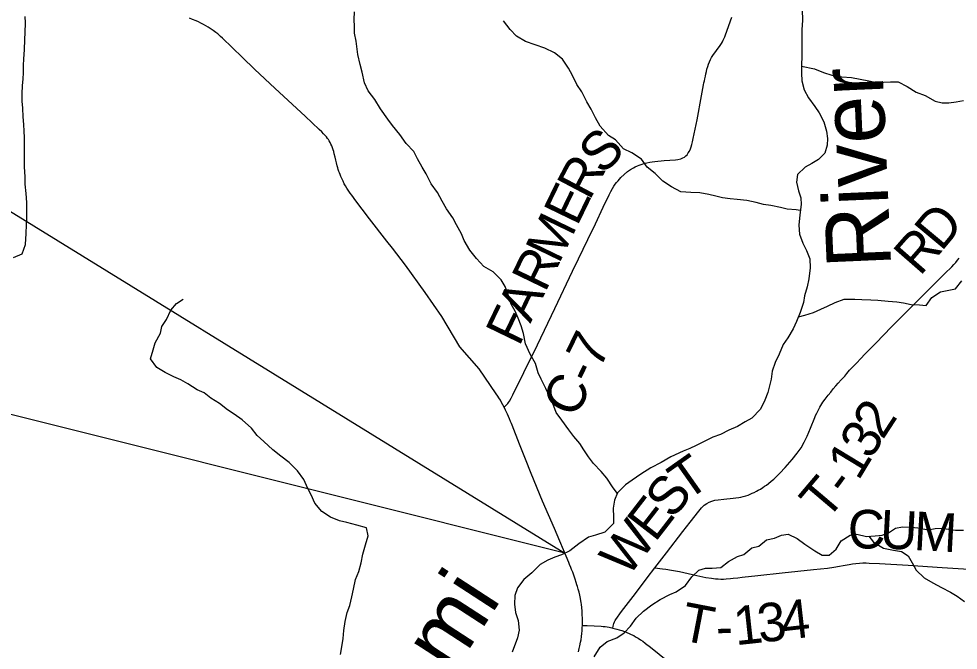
# Model space of a CAD drawing. Extents: x 0 to 48.6, y 0 to 22.
# Drawn here: x 4.141 to 5.524, y 17.631 to 18.56 of the extents above; entities that cross this region are included whole.
import ezdxf

# ---------------------------------------------------------------- set-up
doc = ezdxf.new("R2010")
doc.units = 0
for name, color, linetype in [('GM_X_County_Road', 7, 'Continuous'), ('GM_X_County_Road_Text', 7, 'Continuous'), ('GM_X_Major_River', 7, 'Continuous'), ('GM_X_Major_River_Text', 7, 'Continuous'), ('GM_X_Minor_River', 7, 'Continuous'), ('GM_X_State_Route', 7, 'Continuous'), ('GM_X_Township_Road', 7, 'Continuous'), ('GM_X_Township_Road_Text', 7, 'Continuous'), ('SH_Text', 7, 'Continuous')]:
    doc.layers.add(name, color=color, linetype=linetype)

msp = doc.modelspace()

# ---------------------------------------------------------------- linework, layer by layer
at = {"layer": 'GM_X_County_Road'}
msp.add_lwpolyline([(4.8552, 17.9885), (4.8569, 17.9902), (4.8598, 17.993), (4.8608, 17.994), (4.8619, 17.9954), (4.8632, 17.9975), (4.8656, 18.002), (4.8682, 18.0068), (4.8842, 18.0398), (4.9042, 18.0805), (4.9299, 18.1336), (4.9561, 18.1886), (4.965, 18.207), (4.9787, 18.2356), (4.9898, 18.2585), (5.001, 18.2828), (5.0099, 18.3012), (5.0123, 18.3059), (5.0148, 18.3105), (5.0169, 18.3137), (5.0188, 18.3166), (5.0209, 18.3193), (5.023, 18.3219), (5.0271, 18.3264), (5.032, 18.3311), (5.0371, 18.3354), (5.0411, 18.3383), (5.0458, 18.3411), (5.0482, 18.3423), (5.0514, 18.3438), (5.054, 18.3448), (5.0571, 18.346), (5.0624, 18.3477), (5.0656, 18.3484), (5.0696, 18.3492), (5.0732, 18.3498), (5.0769, 18.3503), (5.0911, 18.3516), (5.1078, 18.3527), (5.111, 18.3531), (5.1153, 18.3542), (5.1183, 18.3554), (5.1206, 18.3567), (5.1227, 18.3583), (5.1245, 18.3602), (5.1264, 18.3627), (5.128, 18.3655), (5.1296, 18.369), (5.1305, 18.3719), (5.1316, 18.375), (5.1326, 18.379), (5.1338, 18.3841), (5.1393, 18.4116), (5.1459, 18.447), (5.1488, 18.4629), (5.1495, 18.4659), (5.1501, 18.469), (5.1507, 18.472), (5.1515, 18.476), (5.1523, 18.4793), (5.153, 18.4826), (5.1538, 18.4859), (5.155, 18.4901), (5.156, 18.4936), (5.1575, 18.497), (5.1589, 18.5003), (5.1606, 18.5032), (5.1623, 18.5061), (5.1734, 18.5211), (5.1752, 18.5241), (5.1767, 18.5264), (5.1777, 18.5286), (5.1789, 18.531), (5.1801, 18.5339), (5.1813, 18.5368), (5.1903, 18.5626)], dxfattribs=at)
at = {"layer": 'GM_X_Major_River'}
msp.add_lwpolyline([(5.2942, 18.5735), (5.2943, 18.5584), (5.2936, 18.544), (5.2934, 18.5318), (5.2934, 18.5151), (5.2936, 18.5049), (5.2929, 18.4924), (5.293, 18.4802), (5.2936, 18.4688), (5.2971, 18.4558), (5.3033, 18.444), (5.3129, 18.4312), (5.3191, 18.4216), (5.3257, 18.4086), (5.33, 18.3948), (5.3313, 18.3842), (5.3307, 18.3743), (5.3274, 18.3626), (5.3181, 18.353), (5.3081, 18.3471), (5.2985, 18.342), (5.2873, 18.3308), (5.2855, 18.3198), (5.2886, 18.3069), (5.2922, 18.2966), (5.2924, 18.2867), (5.2906, 18.2715), (5.2891, 18.2564), (5.29, 18.2431), (5.295, 18.2301), (5.3005, 18.219), (5.3051, 18.2067), (5.306, 18.1938), (5.3041, 18.1775), (5.3012, 18.1658), (5.2975, 18.1526), (5.2958, 18.1428), (5.291, 18.1281), (5.2857, 18.1145), (5.2806, 18.104), (5.2727, 18.0905), (5.266, 18.0808), (5.2604, 18.0668), (5.2545, 18.0541), (5.25, 18.0413), (5.2483, 18.0299), (5.2433, 18.0103), (5.2389, 17.9986), (5.2325, 17.9854), (5.2201, 17.9724), (5.2101, 17.9669), (5.199, 17.9603), (5.186, 17.9549), (5.1737, 17.9483), (5.1626, 17.9443), (5.1476, 17.9371), (5.138, 17.9323), (5.1285, 17.9276), (5.1189, 17.924), (5.1005, 17.9156), (5.0863, 17.9072), (5.0713, 17.8991), (5.0567, 17.8899), (5.044, 17.8811), (5.034, 17.8741), (5.0223, 17.8622), (5.0179, 17.8516), (5.0158, 17.8399), (5.0163, 17.8266), (5.0161, 17.8171), (5.0033, 17.8045), (4.9899, 17.8002), (4.9796, 17.7974), (4.9653, 17.7874), (4.9522, 17.7771), (4.9399, 17.7712), (4.93, 17.7676), (4.9197, 17.7633), (4.9085, 17.7567), (4.8961, 17.7448), (4.8845, 17.7348), (4.8748, 17.7225), (4.8711, 17.7115), (4.8705, 17.6986), (4.8721, 17.6865), (4.8757, 17.6746), (4.8773, 17.6602), (4.8751, 17.6492), (4.8671, 17.6281)], dxfattribs=at)
at = {"layer": 'GM_X_Minor_River'}
for points in [[(4.1328, 18.2087), (4.1458, 18.2142), (4.1506, 18.2282), (4.1515, 18.2441), (4.1521, 18.257), (4.1526, 18.2673), (4.1524, 18.2798), (4.1525, 18.29), (4.1516, 18.303), (4.1502, 18.3166), (4.15, 18.3277), (4.1494, 18.3425), (4.1492, 18.3527), (4.1493, 18.3622), (4.1491, 18.3732), (4.1493, 18.3854), (4.1486, 18.3949), (4.1484, 18.4047), (4.1474, 18.4158), (4.1468, 18.4287), (4.1458, 18.4389), (4.1455, 18.4496), (4.1461, 18.4621), (4.1474, 18.4716), (4.1479, 18.4814), (4.1476, 18.4917), (4.1481, 18.5012), (4.1494, 18.5144), (4.1497, 18.5296), (4.1502, 18.5399), (4.1507, 18.5543), (4.1501, 18.5638)], [(5.0221, 17.8616), (5.016, 17.87), (5.0067, 17.8842), (4.9981, 17.8938), (4.9868, 17.9057), (4.9794, 17.9153), (4.9727, 17.9256), (4.9667, 17.9352), (4.9581, 17.9455), (4.9503, 17.9551), (4.9402, 17.9693), (4.932, 17.9808), (4.9269, 17.9938), (4.9228, 18.0033), (4.9165, 18.0159), (4.9099, 18.0297), (4.9054, 18.0392), (4.9014, 18.0526), (4.8937, 18.0667), (4.8866, 18.0816), (4.8838, 18.0972), (4.8805, 18.1083), (4.8761, 18.1197), (4.8713, 18.13), (4.8658, 18.1403), (4.861, 18.1541), (4.8566, 18.1663), (4.8511, 18.1758), (4.8391, 18.1878), (4.8255, 18.1955), (4.8146, 18.2074), (4.8049, 18.2197), (4.7964, 18.2339), (4.7927, 18.2438), (4.7853, 18.2568), (4.7797, 18.2671), (4.7704, 18.2805), (4.7641, 18.292), (4.7574, 18.3046), (4.7477, 18.3173), (4.7403, 18.3322), (4.7348, 18.3417), (4.7277, 18.3543), (4.7222, 18.365), (4.7113, 18.3766), (4.7016, 18.39), (4.6908, 18.403), (4.684, 18.4126), (4.6732, 18.4279), (4.6651, 18.4413), (4.655, 18.4544), (4.6498, 18.4662), (4.6462, 18.4818), (4.6433, 18.4929), (4.6401, 18.5077), (4.6373, 18.5275), (4.6352, 18.5393), (4.635, 18.5488), (4.6347, 18.559), (4.6349, 18.5704)], [(5.2913, 18.278), (5.2851, 18.2792), (5.2722, 18.2801), (5.2619, 18.2825), (5.2479, 18.2853), (5.2369, 18.287), (5.2263, 18.2898), (5.2127, 18.2926), (5.1983, 18.2943), (5.188, 18.2952), (5.1767, 18.2969), (5.1668, 18.2993), (5.1566, 18.3017), (5.1433, 18.3042), (5.1301, 18.3047), (5.1156, 18.3053), (5.1017, 18.3127), (5.0889, 18.3212), (5.0776, 18.3327), (5.066, 18.3416), (5.0574, 18.3535), (5.0431, 18.3628), (5.031, 18.369), (5.019, 18.3821), (5.0089, 18.3883), (4.9969, 18.4021), (4.9898, 18.4143), (4.9836, 18.4273), (4.9769, 18.438), (4.9695, 18.4526), (4.9624, 18.4633), (4.9561, 18.477), (4.9498, 18.4877), (4.9412, 18.5008), (4.9296, 18.51), (4.9152, 18.517), (4.9012, 18.5218), (4.8865, 18.5269), (4.8733, 18.5347), (4.8643, 18.5447), (4.8542, 18.5573)], [(5.2929, 18.4903), (5.3121, 18.4865), (5.3254, 18.4814), (5.3378, 18.4774), (5.3526, 18.4746), (5.3667, 18.4736), (5.3795, 18.4715), (5.3924, 18.4687), (5.4034, 18.4663), (5.4137, 18.4669), (5.4243, 18.4676), (5.4353, 18.4674), (5.4485, 18.4608), (5.4621, 18.4523), (5.4753, 18.4475), (5.4896, 18.439), (5.5002, 18.4366), (5.5101, 18.4364), (5.5208, 18.4378), (5.5314, 18.44)], [(5.2885, 18.1217), (5.2982, 18.1241), (5.3108, 18.1281), (5.3215, 18.1329), (5.3314, 18.1373), (5.3425, 18.1425), (5.3559, 18.1477), (5.3714, 18.1474), (5.3821, 18.1469), (5.395, 18.1464), (5.4056, 18.1459), (5.4208, 18.1445), (5.4333, 18.1436), (5.4431, 18.142), (5.4545, 18.1395), (5.467, 18.139), (5.4765, 18.1381), (5.4847, 18.1502), (5.4977, 18.1583), (5.5076, 18.1605), (5.5198, 18.1626), (5.529, 18.1743)], [(4.6146, 17.6243), (4.6163, 17.6356), (4.6184, 17.6481), (4.6193, 17.6599), (4.6214, 17.6731), (4.6242, 17.6864), (4.6281, 17.6966), (4.6313, 17.7095), (4.6334, 17.7208), (4.6366, 17.7348), (4.6413, 17.7465), (4.6449, 17.7594), (4.6474, 17.7719), (4.6514, 17.7859), (4.655, 17.7991), (4.6528, 17.8109), (4.6385, 17.8149), (4.6237, 17.8189), (4.6127, 17.8213), (4.5999, 17.8264), (4.5867, 17.8349), (4.5766, 17.8472), (4.5711, 17.8594), (4.5663, 17.869), (4.5603, 17.882), (4.551, 17.8946), (4.5387, 17.9073), (4.5266, 17.9162), (4.515, 17.9255), (4.5015, 17.9378), (4.4917, 17.947), (4.4835, 17.9574), (4.4696, 17.9697), (4.4579, 17.9782), (4.4481, 17.9844), (4.4361, 17.9941), (4.4233, 18.0018), (4.4135, 18.0095), (4.4033, 18.0142), (4.3894, 18.0231), (4.3792, 18.029), (4.369, 18.0333), (4.3562, 18.0395), (4.3438, 18.0469), (4.3348, 18.0599), (4.3384, 18.0731), (4.3416, 18.0834), (4.3494, 18.0973), (4.3514, 18.1071), (4.3584, 18.1177), (4.3646, 18.1313), (4.3728, 18.141), (4.3827, 18.1474)], [(4.9876, 17.6209), (4.9969, 17.6353), (5.0069, 17.6435), (5.0214, 17.649), (5.0321, 17.6561), (5.0414, 17.6662), (5.0499, 17.6778), (5.0606, 17.688), (5.0729, 17.6977), (5.0848, 17.7055), (5.099, 17.7129), (5.1085, 17.7166), (5.1223, 17.7259), (5.1316, 17.7387), (5.142, 17.7488), (5.1519, 17.7513), (5.1614, 17.7516), (5.1743, 17.7525), (5.1855, 17.7615), (5.1988, 17.7685), (5.2084, 17.7715), (5.2199, 17.7816), (5.2302, 17.7837), (5.2417, 17.793), (5.2535, 17.7955), (5.2638, 17.8), (5.2734, 17.8017), (5.2866, 17.7951), (5.2982, 17.787), (5.3125, 17.7769), (5.3235, 17.7707), (5.3337, 17.7706), (5.3441, 17.7796), (5.3515, 17.792), (5.3645, 17.8002), (5.3744, 17.8016), (5.3888, 17.7983), (5.4017, 17.7993), (5.4116, 17.8), (5.4211, 17.8036), (5.4315, 17.8103), (5.4418, 17.8125), (5.4547, 17.8119), (5.4645, 17.8107), (5.4793, 17.8078), (5.4896, 17.8099), (5.4999, 17.8102), (5.5093, 17.8089), (5.5196, 17.8077), (5.5317, 17.8075)], [(5.3921, 17.7986), (5.3993, 17.7899), (5.414, 17.7809), (5.4284, 17.7781), (5.4405, 17.776), (5.4503, 17.7695), (5.4559, 17.7595), (5.4618, 17.7484), (5.4738, 17.7373), (5.4862, 17.7299), (5.4991, 17.7233), (5.5123, 17.7163), (5.5224, 17.7101), (5.533, 17.7023)]]:
    msp.add_lwpolyline(points, dxfattribs=at)
at = {"layer": 'GM_X_State_Route'}
for points in [[(4.9294, 17.8097), (4.912, 17.8503), (4.8952, 17.8911), (4.8868, 17.9118), (4.8778, 17.9343), (4.8671, 17.9621), (4.8661, 17.9644), (4.8649, 17.9672), (4.8632, 17.9712), (4.8616, 17.9749), (4.8602, 17.978), (4.8587, 17.9813), (4.8574, 17.9842), (4.8552, 17.9885), (4.8536, 17.992), (4.8516, 17.9954), (4.8497, 17.999), (4.8476, 18.0023), (4.8459, 18.0049), (4.8437, 18.0084), (4.8183, 18.0452), (4.7899, 18.0772), (4.7637, 18.1222), (4.7391, 18.1573), (4.71, 18.1976), (4.6908, 18.2228), (4.6827, 18.2329), (4.6572, 18.2659), (4.6356, 18.294), (4.6333, 18.2971), (4.6309, 18.3005), (4.6286, 18.3035), (4.6258, 18.3079), (4.6238, 18.3108), (4.6218, 18.3143), (4.62, 18.3173), (4.6181, 18.3211), (4.6166, 18.324), (4.615, 18.3279), (4.6137, 18.3309), (4.6128, 18.3334), (4.6121, 18.3355), (4.611, 18.3386), (4.6104, 18.341), (4.6097, 18.3437), (4.6085, 18.3483), (4.6076, 18.3522), (4.6065, 18.3568), (4.6053, 18.3616), (4.6044, 18.3647), (4.6036, 18.3675), (4.6025, 18.3704), (4.6014, 18.3732), (4.6002, 18.3758), (4.599, 18.3782), (4.5977, 18.3804), (4.5965, 18.3824), (4.5952, 18.3842), (4.5936, 18.3863), (4.5917, 18.3885), (4.5896, 18.3909), (4.5869, 18.3937), (4.5831, 18.3975), (4.5622, 18.4171), (4.5183, 18.4574), (4.488, 18.486), (4.4702, 18.5033), (4.4551, 18.5181), (4.4407, 18.5318), (4.4377, 18.5344), (4.4337, 18.5379), (4.4308, 18.5402), (4.4269, 18.5432), (4.424, 18.5452), (4.4198, 18.548), (4.4163, 18.55), (4.4128, 18.552), (4.4089, 18.5539), (4.4051, 18.5558), (4.4018, 18.5572), (4.3965, 18.5594), (4.392, 18.5611)], [(4.9649, 17.6286), (4.9659, 17.6332), (4.9668, 17.6371), (4.9678, 17.6424), (4.9685, 17.6462), (4.9691, 17.6507), (4.9697, 17.6554), (4.97, 17.6592), (4.9704, 17.664), (4.9705, 17.6672), (4.9706, 17.6684), (4.9707, 17.672), (4.9707, 17.6759), (4.9706, 17.6788), (4.9704, 17.6817), (4.9703, 17.6842), (4.97, 17.6881), (4.9695, 17.6935), (4.969, 17.6979), (4.9685, 17.7008), (4.9681, 17.7033), (4.9675, 17.7071), (4.9665, 17.7119), (4.9656, 17.7161), (4.9643, 17.7207), (4.9633, 17.7245), (4.9625, 17.7272), (4.9615, 17.7302), (4.96, 17.7351), (4.9589, 17.7381), (4.9578, 17.7411), (4.9562, 17.7456), (4.9546, 17.7495), (4.9535, 17.7523), (4.9517, 17.7568), (4.9505, 17.7598), (4.9294, 17.8097)], [(4.9705, 17.6672), (4.9777, 17.6669), (4.9982, 17.6661), (5.001, 17.6658), (5.0038, 17.6655), (5.0071, 17.665), (5.01, 17.6645), (5.0137, 17.6637), (5.0154, 17.6633), (5.0174, 17.6629), (5.021, 17.6619), (5.0246, 17.6609), (5.0284, 17.6596), (5.0323, 17.6583), (5.0359, 17.6568), (5.0392, 17.6554), (5.0423, 17.6539), (5.046, 17.6522), (5.0489, 17.6506), (5.0526, 17.6485), (5.056, 17.6462), (5.0594, 17.644), (5.0629, 17.6413), (5.066, 17.6389), (5.0683, 17.6371), (5.0987, 17.6125)]]:
    msp.add_lwpolyline(points, dxfattribs=at)
at = {"layer": 'GM_X_Township_Road'}
for points in [[(5.077, 17.7519), (5.0943, 17.774), (5.1185, 17.8056), (5.1291, 17.8193), (5.1417, 17.8356), (5.1458, 17.8403), (5.1479, 17.8422), (5.15, 17.8442), (5.1536, 17.8468), (5.157, 17.8487), (5.1611, 17.8503), (5.1654, 17.8515), (5.1704, 17.8523), (5.1785, 17.8532), (5.1927, 17.8545), (5.1966, 17.855), (5.2006, 17.8555), (5.2038, 17.8561), (5.2072, 17.8569), (5.211, 17.858), (5.2143, 17.8591), (5.2173, 17.8604), (5.2205, 17.8617), (5.2234, 17.8628), (5.2266, 17.8647), (5.2294, 17.8662), (5.2325, 17.868), (5.2359, 17.8701), (5.2387, 17.872), (5.2413, 17.8739), (5.2447, 17.8763), (5.2485, 17.8794), (5.2524, 17.8826), (5.2611, 17.8913), (5.2691, 17.8999), (5.2792, 17.9117), (5.2866, 17.9208), (5.2924, 17.9288), (5.2971, 17.9368), (5.3015, 17.9456), (5.3065, 17.9576), (5.3126, 17.9732), (5.3139, 17.9761), (5.3154, 17.9795), (5.317, 17.9828), (5.3184, 17.9856), (5.3199, 17.9883), (5.3215, 17.991), (5.3246, 17.9957), (5.3281, 18.0003), (5.3325, 18.0061), (5.3361, 18.0106), (5.3399, 18.0153), (5.3438, 18.0198), (5.3472, 18.0238), (5.3515, 18.0286), (5.3568, 18.0344), (5.3598, 18.0381), (5.3639, 18.0431), (5.3685, 18.0479), (5.3749, 18.0545), (5.3794, 18.0592), (5.3871, 18.0673), (5.3972, 18.0774), (5.4029, 18.0831), (5.4253, 18.1063), (5.4437, 18.1248), (5.48, 18.1612), (5.4924, 18.1735), (5.5043, 18.1853), (5.5144, 18.1953), (5.5174, 18.1986), (5.5202, 18.2016), (5.5227, 18.2047), (5.5253, 18.2078)], [(5.077, 17.7519), (5.0883, 17.7506), (5.0932, 17.7501), (5.1018, 17.7488), (5.1134, 17.7465), (5.1389, 17.7407), (5.1522, 17.738), (5.1608, 17.7366), (5.1664, 17.736), (5.1705, 17.7356), (5.1744, 17.7354), (5.1784, 17.7355), (5.1824, 17.7356), (5.1886, 17.7362), (5.1923, 17.7366), (5.1991, 17.7374), (5.2059, 17.7381), (5.2287, 17.7408), (5.2646, 17.7446), (5.3109, 17.7494), (5.3313, 17.7516), (5.3405, 17.7529), (5.3491, 17.7543), (5.3546, 17.7554), (5.3632, 17.757), (5.368, 17.7578), (5.3729, 17.7586), (5.3785, 17.7591), (5.3835, 17.7592), (5.3881, 17.7592), (5.3928, 17.7591), (5.4077, 17.7582), (5.4499, 17.7558), (5.5001, 17.7525), (5.5552, 17.7492)], [(5.0154, 17.6633), (5.016, 17.666), (5.017, 17.6701), (5.0178, 17.6724), (5.0186, 17.6744), (5.0197, 17.6762), (5.0283, 17.6877), (5.0485, 17.7144), (5.0657, 17.7373), (5.077, 17.7519)]]:
    msp.add_lwpolyline(points, dxfattribs=at)
at = {"layer": 'SH_Text'}
msp.add_lwpolyline([(3.8757, 18.4323), (4.9445, 17.7738), (3.8757, 18.0412)], close=True, dxfattribs=at)

# ---------------------------------------------------------------- texts
at = {"layer": 'GM_X_County_Road_Text'}
for s, height, rotation, p in [('S', 0.0568, 45.1982, (5.0001, 18.3291)), ('R', 0.0568, 62.1851, (4.981, 18.2914)), ('E', 0.0568, 64.1901, (4.9627, 18.2536)), ('M', 0.0568, 64.2168, (4.9359, 18.1981)), ('R', 0.0568, 64.2135, (4.9156, 18.1561)), ('A', 0.0568, 64.2137, (4.8939, 18.1111)), ('F', 0.0568, 64.2169, (4.8772, 18.0766)), ('C-7', 0.05682, 64.0471, (4.9604, 17.9706))]:
    msp.add_text(s, height=height, rotation=rotation, dxfattribs=at).set_placement(p)
at = {"layer": 'GM_X_Major_River_Text'}
for s, rotation, p in [('River', 92.4956, (5.4251, 18.1955)), ('Miami', 57.0037, (4.6682, 17.423))]:
    msp.add_text(s, height=0.0947, rotation=rotation, dxfattribs=at).set_placement(p)
at = {"layer": 'GM_X_Township_Road_Text'}
for s, rotation, p in [('D', 50.1851, (5.4989, 18.2164)), ('R', 48.8361, (5.4673, 18.1802)), ('2', 56.9161, (5.4126, 17.9394)), ('3', 59.8068, (5.3954, 17.9098)), ('1', 58.7932, (5.3767, 17.8789)), ('T', 35.1546, (5.1238, 17.8491)), ('S', 51.9583, (5.1034, 17.822)), ('T', 49.7297, (5.3296, 17.8198)), ('-', 53.4536, (5.3595, 17.8554)), ('E', 52.2498, (5.0774, 17.7884)), ('W', 52.2619, (5.0371, 17.7364)), ('C', 1.5496, (5.3621, 17.7797)), ('U', 356.9459, (5.4075, 17.781)), ('M', 356.8677, (5.4574, 17.7784)), ('4', 6.5196, (5.266, 17.6457)), ('T', 349.0565, (5.1126, 17.6461)), ('1', 6.2797, (5.1962, 17.6379)), ('3', 6.4557, (5.2312, 17.6417)), ('-', 1.437, (5.1676, 17.6369))]:
    msp.add_text(s, height=0.0568, rotation=rotation, dxfattribs=at).set_placement(p)

doc.saveas('drawing.dxf')
